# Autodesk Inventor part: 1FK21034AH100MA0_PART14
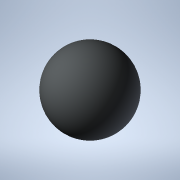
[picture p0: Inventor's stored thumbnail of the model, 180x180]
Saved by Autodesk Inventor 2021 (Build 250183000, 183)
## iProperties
Created: 2025-04
Part Number: 1FK21034AH100MA0_PART14
Material: Generic
Catalog Web Link: www.3dfindit.com
Description: -Servo synchronous motor
Document SubType Name: Modeling
Designer: psAdmin
Mass: 0.113097 g
Surface Area: 1.13097 cm^2
Volume: 0.113097 cm^3
Density: 1 g/cm^3
Appearance: PSOLRGB-212-217-219
Category: PARTsolutions
Title: 1FK21034AH100MA0_PART14
Author: Cadenas PARTsolutions
Comments: Servo synchronous motor
Sending System: PARTsolutions
Preprocessor: ST-DEVELOPER v19.3
PSOL_IDENT_0: {$CADENAS_DATA/23d-libs/siemens_ag/_cat_/39/97/1fk21034ah100ma0.prj},216 {VTYP=3D},{NB=1FK21034AH100
PSOL_IDENT_1: MA0_PART14},{LINA=1FK21034AH100MA0_PART14},{NN=1FK21034AH100MA0_PART14},{NOPRJ=TRUE},{DATE=19.08.202
PSOL_IDENT_2: 5 14:00:33},{GEOMDATE=30.07.2025 02:02:21},{VERSION=},{LINEID=10},{WBVAR=},{WBNUMERIC=}  {NB=1FK2103
PSOL_IDENT_3: 4AH100MA0_PART14},{LINA=1FK21034AH100MA0_PART14},{KT=DUMMY},{PREVIEW=../../../_pool_/d3/78/p_d211_xx
PSOL_IDENT_4: _00934j.png},{DESCSHORT=SIMOTICS S-1FK2 HD, SINAMICS S210 3AC 400V-480V, 1.01 Nm, 4500 rpm},{DESCLON
PSOL_IDENT_5: G=SIMOTICS S-1FK2 HD servo motor M0=1.27 Nm; PN = 0.48 kW at nN=4500 rpm (380-480 V); PN = 0.3 kW at
PSOL_IDENT_6: nN=2500 rpm (200-240 V); with holding brake; degree of protection IP64; cylindrical shaft D14 x 30
PSOL_IDENT_7: mm; absolute encoder 22-bit + 12-bit multiturn (encoder AM22DQC); with OCC interface; plug size M17,
PSOL_IDENT_8: rotatable; SIMOTICS S-1FK2 servomotorfor a wide range of uses in industrial environments. SIMOTICS
PSOL_IDENT_9: S‑1FK2 servomotors are compact synchronous motors with a high dynamic performance that set themselve
PSOL_IDENT_10: s apart as a result of their high power density, degree of protection and overload capability. The m
PSOL_IDENT_11: otors are available in two variants: as High Dynamic variant (highest dynamic performance as a resul
PSOL_IDENT_12: t of the low intrinsic moment of inertia for applications demanding a high dynamic performance with
PSOL_IDENT_13: low moved masses) - and as Compact variant (precise and stable closed-loop control for medium up to
PSOL_IDENT_14: large moved masses as a result of a medium intrinsic moment of inertia). SIMOTICSS‑1FK2 servomotors
PSOL_IDENT_15: fully exploit their strengths in a system with the SINAMICSS210 frequency converter and simple conne
PSOL_IDENT_16: ction using the one cable connection (OCC). Advantages include the short control and positioning tim
PSOL_IDENT_17: es, fast and precise correction of disturbing quantities as well as stable control with a high dynam
PSOL_IDENT_18: ic performance. The servo motors can be configured to address a wide range of requirements. For exam
PSOL_IDENT_19: ple with and without holding brake, IP64 or IP65 degree of protection, singleturn or multiturn absol
PSOL_IDENT_20: ute encoders - to name just a few. Further, the servomotors are available in different shaft heights
PSOL_IDENT_21: extending from 20 to 100. A shaft sealing ring is available to achieve an IP65 degree of protection
PSOL_IDENT_22: and for subsequent mounting at the motor or as spare part. SIMOTICS - the optimum motor for each an
PSOL_IDENT_23: d every motion control application.},{INTNO=195125454019},{SUPPLIERALTNO=1FK2103-4AH10-0MA0},{MANUID=
PSOL_IDENT_24: 1FK21034AH100MA0},{MANUNAME=Siemens},{MANUTYPEDESC=SYNCHRONOUS MOTOR 1FK2 HD 1,27 NM},{AAU732=SIMOTI
PSOL_IDENT_25: CS},{AAO057=S-1FK2},{AAU734=SIMOTICS S-1FK2 HD servo motor M0=1.27 Nm; PN = 0.48 kW at nN=4500 rpm (
PSOL_IDENT_26: 380-480 V); PN = 0.3 kW at nN=2500 rpm (200-240 V); with holding brake; degree of protection IP64; c
PSOL_IDENT_27: ylindrical shaft D14 x 30 mm; absolute encoder 22-bit + 12-bit multiturn (encoder AM22DQC); with OCC
PSOL_IDENT_28: interface; plug size M17, rotatable;},{AAW338=SYNCHRONOUS MOTOR 1FK2 HD 1,27 NM},{AAO742=SIMOTICS},
PSOL_IDENT_29: {AAO663=4034106444921},{NOCUPEROU=1},{PRICEQUANTITY=1},{QUANTITYMIN=1},{QUANTITYINT=1},{CTN=85015100
PSOL_IDENT_30: },{COO=RO},{AAO676=1FK2103-4AH10-0MA0},{AAO677=Siemens AG},{ORDERUNIT=C62},{CONTENTUNIT=C62}
NB: 1FK21034AH100MA0_PART14
NT: Servo synchronous motor
NBSYN: $MANUID._PART14
LINA: 1FK21034AH100MA0_PART14
CATALOG: SIEMENS
PREVIEW: ../../../_pool_/d3/78/p_d211_xx_00934j.png
DESCSHORT: SIMOTICS S-1FK2 HD, SINAMICS S210 3AC 400V-480V, 1.01 Nm, 4500 rpm
DESCLONG: SIMOTICS S-1FK2 HD servo motor M0=1.27 Nm; PN = 0.48 kW at nN=4500 rpm (380-480 V); PN = 0.3 kW at nN=2500 rpm (200-240 V); with holding brake; degree of protec
INTNO: 195125454019
SUPPLIERALTNO: 1FK2103-4AH10-0MA0
MANUID: 1FK21034AH100MA0
MANUNAME: Siemens
MANUTYPEDESC: SYNCHRONOUS MOTOR 1FK2 HD 1,27 NM
AAU732: SIMOTICS
AAO057: S-1FK2
AAU734: SIMOTICS S-1FK2 HD servo motor M0=1.27 Nm; PN = 0.48 kW at nN=4500 rpm (380-480 V); PN = 0.3 kW at nN=2500 rpm (200-240 V); with holding brake; degree of protec
AAW338: SYNCHRONOUS MOTOR 1FK2 HD 1,27 NM
AAO742: SIMOTICS
AAO663: 4034106444921.0
NOCUPEROU: 1
PRICEQUANTITY: 1
QUANTITYMIN: 1
QUANTITYINT: 1
CTN: 85015100
COO: RO
ARTICLENO: 1FK21034AH100MA0_PART14
BOMINFO: 1FK21034AH100MA0_PART14
CREATOR: CADENAS GmbH
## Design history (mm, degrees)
feature "2025_04_17_15_09_00_0361"
body "Solid1"
